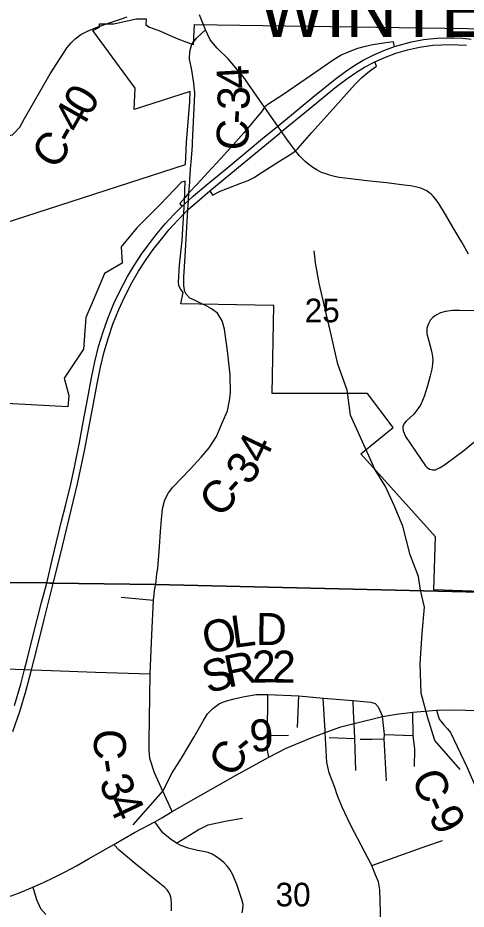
# Model space of a CAD drawing. Extents: x 0 to 34, y 0 to 22.
# Drawn here: x 5.55 to 6.345, y 15.187 to 16.768 of the extents above; entities that cross this region are included whole.
import ezdxf

# ---------------------------------------------------------------- set-up
doc = ezdxf.new("R2010")
doc.units = 0
for name, color, linetype in [('GM_X_City_Street', 7, 'Continuous'), ('GM_X_Corporation', 7, 'Continuous'), ('GM_X_Corporation_Text', 7, 'Continuous'), ('GM_X_County_Road', 7, 'Continuous'), ('GM_X_County_Road_Text', 7, 'Continuous'), ('GM_X_Interchange_Ramps', 7, 'Continuous'), ('GM_X_Minor_River', 7, 'Continuous'), ('GM_X_Section_Text', 7, 'Continuous'), ('GM_X_State_Route', 7, 'Continuous'), ('GM_X_Township_Road', 7, 'Continuous'), ('GM_X_US_Route', 7, 'Continuous')]:
    doc.layers.add(name, color=color, linetype=linetype)

msp = doc.modelspace()

# ---------------------------------------------------------------- linework, layer by layer
at = {"layer": 'GM_X_City_Street'}
msp.add_lwpolyline([(6.3629, 16.2484), (6.3334, 16.2491), (6.3214, 16.249), (6.3088, 16.2475), (6.2999, 16.2448), (6.2909, 16.2404), (6.2864, 16.2369), (6.2821, 16.2324), (6.2785, 16.2254), (6.2756, 16.2176), (6.2754, 16.2126), (6.2757, 16.2078), (6.2784, 16.1973), (6.2834, 16.1791), (6.2854, 16.1713), (6.2861, 16.1624), (6.2855, 16.1542), (6.2844, 16.145), (6.2815, 16.133), (6.2767, 16.1154), (6.271, 16.0965), (6.2648, 16.0826), (6.2595, 16.0746), (6.2524, 16.0653), (6.239, 16.053), (6.2353, 16.0485), (6.2332, 16.0434), (6.233, 16.0398), (6.2337, 16.0356), (6.2353, 16.0313), (6.2378, 16.0259), (6.2731, 15.9738), (6.2764, 15.9705), (6.2803, 15.9677), (6.2855, 15.9662), (6.2908, 15.9664), (6.2992, 15.9705), (6.3068, 15.9754), (6.3279, 15.9905), (6.3412, 16.0009), (6.359, 16.0156)], dxfattribs=at)
at = {"layer": 'GM_X_Corporation'}
for points in [[(5.5242, 16.4033), (5.8477, 16.5082), (5.849, 16.5474), (5.8549, 16.6198), (5.8559, 16.6377), (5.7562, 16.6054), (5.7582, 16.6432), (5.6829, 16.7458), (5.6949, 16.7513), (5.695, 16.7575), (5.7204, 16.7575), (5.7598, 16.7663), (5.7775, 16.7663), (5.7771, 16.7554), (5.7838, 16.7518), (5.8029, 16.7442), (5.8309, 16.7322), (5.8462, 16.7264), (5.8617, 16.7206), (5.8618, 16.7216), (5.8633, 16.7565), (6.5495, 16.7462)], [(6.4714, 15.7474), (6.2879, 15.7537), (6.2911, 15.8475), (6.1587, 15.995), (6.2161, 16.0418), (6.1705, 16.1017), (6.001, 16.1021), (6.004, 16.258), (5.839, 16.2611), (5.8435, 16.281), (5.8378, 16.288), (5.8356, 16.2934), (5.8349, 16.2995), (5.8367, 16.3298), (5.8414, 16.3732), (5.8426, 16.3937), (5.8456, 16.4419), (5.8468, 16.4782), (5.8405, 16.4764), (5.8026, 16.4372), (5.761, 16.3957), (5.7334, 16.3617), (5.7349, 16.3331), (5.7037, 16.3144), (5.6835, 16.2669), (5.6707, 16.2368), (5.6667, 16.1803), (5.6321, 16.129), (5.6403, 16.0983), (5.6386, 16.0784), (5.5079, 16.0853)], [(5.4664, 15.7674), (5.6014, 15.7658), (5.6068, 15.7657), (5.6123, 15.7657), (5.7944, 15.7634), (6.4702, 15.7474), (6.8105, 15.7443), (6.8653, 15.7428), (6.9267, 15.7411), (7.0294, 15.7382), (7.1916, 15.7337), (7.2174, 15.7331), (7.2238, 15.7321), (7.3532, 15.7283), (7.8346, 15.7173), (8.2379, 15.708), (8.2436, 15.7079), (8.2556, 15.7096), (8.4088, 15.7047), (8.4164, 15.7046), (8.9, 15.6953), (8.9, 16.3396)], [(4.5503, 14.1), (8.9, 14.1), (8.9, 15.6953), (8.4164, 15.7046), (8.4088, 15.7047), (8.2556, 15.7096), (8.2436, 15.7079), (8.2379, 15.708), (7.8346, 15.7173), (7.3532, 15.7283), (7.2238, 15.7321), (7.2174, 15.7331), (7.1916, 15.7337), (7.0294, 15.7382), (6.9267, 15.7411), (6.8653, 15.7428), (6.8105, 15.7443), (6.4702, 15.7474), (5.7944, 15.7634), (5.6123, 15.7657), (5.6068, 15.7657), (5.6014, 15.7658), (5.4664, 15.7674)]]:
    msp.add_lwpolyline(points, dxfattribs=at)
at = {"layer": 'GM_X_County_Road'}
for p, q in [((5.8684, 16.7333), (5.8827, 16.7466)), ((5.8575, 16.5117), (5.8596, 16.5418))]:
    msp.add_line(p, q, dxfattribs=at)
for points in [[(5.671, 16.7433), (5.6735, 16.7446), (5.6892, 16.7508), (5.7074, 16.7573)], [(5.7074, 16.7573), (5.732, 16.7659), (5.7439, 16.7699)], [(5.3928, 16.5372), (5.3985, 16.541), (5.4132, 16.5466), (5.4712, 16.5579), (5.4999, 16.5533), (5.5403, 16.5604), (5.5534, 16.5743), (5.562, 16.5897), (5.6072, 16.6686), (5.6376, 16.7153), (5.6445, 16.724), (5.6518, 16.7306), (5.662, 16.7387), (5.671, 16.7433)], [(5.8635, 16.6394), (5.8624, 16.6525), (5.8585, 16.6755), (5.8548, 16.6953), (5.855, 16.7085), (5.8587, 16.7212), (5.8617, 16.7251), (5.8622, 16.7258)], [(5.8622, 16.7258), (5.867, 16.732), (5.8677, 16.7327), (5.8684, 16.7333)], [(5.8596, 16.5418), (5.86, 16.5468), (5.864, 16.6334), (5.8638, 16.6364), (5.8635, 16.6394)], [(5.8554, 16.4825), (5.8571, 16.5067), (5.8575, 16.5117)], [(5.8467, 16.345), (5.8515, 16.4273), (5.8527, 16.4444), (5.8536, 16.4576), (5.855, 16.4767), (5.8554, 16.4825)], [(5.8445, 16.296), (5.8447, 16.3088), (5.8467, 16.345)], [(5.8649, 16.2667), (5.8552, 16.2712), (5.8487, 16.2779), (5.8458, 16.2841), (5.8455, 16.2861), (5.8445, 16.293), (5.8445, 16.296)], [(5.7944, 15.7619), (5.7946, 15.7629), (5.7968, 15.7819), (5.7983, 15.7921), (5.8013, 15.8302), (5.8028, 15.8573), (5.8046, 15.8784), (5.8069, 15.8976), (5.811, 15.9133), (5.8175, 15.9258), (5.825, 15.9359), (5.8558, 15.9674), (5.8754, 15.9889), (5.8894, 16.0057), (5.9024, 16.0255), (5.9131, 16.051), (5.9222, 16.0714), (5.9258, 16.0897), (5.9271, 16.1029), (5.9265, 16.1348), (5.9222, 16.1778), (5.9168, 16.2158), (5.9123, 16.2309), (5.9041, 16.2441), (5.8935, 16.2521), (5.8853, 16.2567), (5.8755, 16.2617), (5.8649, 16.2667)], [(5.8236, 15.3605), (5.8072, 15.3964), (5.7925, 15.4292), (5.7841, 15.4543), (5.7828, 15.4694), (5.7828, 15.485), (5.7848, 15.6046), (5.7878, 15.6738), (5.7908, 15.7354), (5.7923, 15.7513), (5.7939, 15.759), (5.7944, 15.7619)], [(5.7544, 15.3372), (5.8072, 15.3964), (5.8238, 15.4292), (5.8405, 15.455), (5.8628, 15.4927), (5.8796, 15.5218), (5.8866, 15.5335), (5.8958, 15.5435), (5.9075, 15.5519), (5.9201, 15.5567), (5.9339, 15.5606), (5.9492, 15.5638), (5.9729, 15.5678), (5.9935, 15.568), (6.0483, 15.5654), (6.0915, 15.5616), (6.1449, 15.5575), (6.1766, 15.5545), (6.184, 15.5519), (6.1893, 15.5463), (6.1972, 15.5291)], [(6.1972, 15.5291), (6.2221, 15.533), (6.2511, 15.5366), (6.2927, 15.5405)], [(6.2927, 15.5405), (6.3175, 15.541), (6.371, 15.5398), (6.4077, 15.5372), (6.4382, 15.5331), (6.4667, 15.529)], [(6.2927, 15.5405), (6.2978, 15.5242), (6.3003, 15.5205), (6.3061, 15.514), (6.3122, 15.5073), (6.3174, 15.5004), (6.3474, 15.4383), (6.3618, 15.4045), (6.3711, 15.3851), (6.3807, 15.3689), (6.3866, 15.3614), (6.3929, 15.3557), (6.4036, 15.3508), (6.4096, 15.3495), (6.4166, 15.3492), (6.4241, 15.35), (6.4307, 15.3528), (6.4469, 15.3618), (6.4675, 15.3746), (6.5022, 15.3966), (6.5132, 15.4033)], [(5.8236, 15.3605), (5.8745, 15.3895), (5.936, 15.4246), (5.9665, 15.4409), (5.9954, 15.4572), (6.0262, 15.4727), (6.0702, 15.4914), (6.0951, 15.5007), (6.123, 15.5106), (6.1467, 15.5165), (6.1972, 15.5291)], [(5.7933, 15.3424), (5.8053, 15.3493), (5.8236, 15.3605)], [(5.72, 15.3019), (5.757, 15.3234), (5.7933, 15.3424)], [(5.5765, 15.2264), (5.5955, 15.2347), (5.6141, 15.2433), (5.6339, 15.2535), (5.654, 15.2644), (5.6751, 15.2766), (5.72, 15.3019)], [(5.8227, 15.1841), (5.8226, 15.197), (5.8219, 15.2062), (5.8202, 15.2125), (5.8175, 15.2179), (5.8149, 15.2214), (5.811, 15.2256), (5.8021, 15.233), (5.7594, 15.2674), (5.73, 15.2917), (5.72, 15.3019)], [(5.4875, 15.1929), (5.5249, 15.2062), (5.5509, 15.2158), (5.5765, 15.2264)]]:
    msp.add_lwpolyline(points, dxfattribs=at)
at = {"layer": 'GM_X_Interchange_Ramps'}
for points in [[(6.2181, 16.7174), (6.2164, 16.7253), (6.1989, 16.723), (6.1798, 16.7202), (6.1663, 16.7175), (6.1525, 16.7137), (6.1388, 16.7086), (6.1239, 16.7017), (6.1097, 16.6931), (6.096, 16.6835), (6.0595, 16.6589), (6.0202, 16.6318), (5.9938, 16.6145), (5.9876, 16.6096)], [(6.0424, 16.5325), (6.047, 16.5366), (6.0717, 16.5647), (6.1036, 16.6001), (6.1484, 16.6505), (6.1605, 16.6624), (6.1709, 16.6713), (6.1802, 16.6781), (6.1866, 16.6824), (6.1832, 16.6901)], [(5.9876, 16.6096), (5.9832, 16.6034), (5.9724, 16.5897), (5.9508, 16.5643), (5.9319, 16.5427), (5.9102, 16.5189), (5.8871, 16.4938), (5.868, 16.473), (5.8536, 16.4576), (5.8461, 16.4491)], [(5.8907, 16.4614), (5.8953, 16.4538), (5.9091, 16.4605), (5.9214, 16.4655), (5.9456, 16.4748), (5.9584, 16.4799), (5.9691, 16.4851), (5.9772, 16.49), (6.0095, 16.5108), (6.0363, 16.5274), (6.0424, 16.5325)], [(5.8461, 16.4491), (5.8372, 16.4389), (5.8409, 16.4335)]]:
    msp.add_lwpolyline(points, dxfattribs=at)
at = {"layer": 'GM_X_Minor_River'}
msp.add_lwpolyline([(6.3347, 15.4348), (6.2896, 15.4862), (6.2767, 15.5282), (6.2658, 15.5702), (6.2641, 15.6226), (6.2673, 15.6766), (6.2713, 15.7231), (6.2644, 15.753), (6.2609, 15.7772), (6.2463, 15.8157), (6.2332, 15.8668), (6.2175, 15.9034), (6.2021, 15.937), (6.1842, 15.9663), (6.1641, 16.0109), (6.1401, 16.0637), (6.1344, 16.108), (6.1177, 16.1537), (6.1063, 16.2037), (6.0952, 16.2514), (6.0849, 16.2976), (6.0779, 16.3336), (6.0769, 16.3446), (6.0756, 16.3548)], dxfattribs=at)
at = {"layer": 'GM_X_State_Route'}
for points in [[(5.9876, 16.6096), (5.9495, 16.6643), (5.9232, 16.6955), (5.9035, 16.7144), (5.8915, 16.7293), (5.8827, 16.7466), (5.8722, 16.7737)], [(6.0257, 16.5555), (6.0179, 16.5663), (6.0111, 16.5759), (5.9876, 16.6096)], [(6.0796, 16.499), (6.0736, 16.5026), (6.0662, 16.5081), (6.0598, 16.5133), (6.0496, 16.5231), (6.0424, 16.5325), (6.0257, 16.5555)], [(6.3496, 16.3492), (6.3375, 16.3704), (6.3219, 16.397), (6.3088, 16.4194), (6.2972, 16.4386), (6.2924, 16.4454), (6.2868, 16.4521), (6.2834, 16.4554), (6.2793, 16.4586), (6.2757, 16.4612), (6.2717, 16.4633), (6.2651, 16.466), (6.2582, 16.468), (6.2467, 16.4701), (6.2353, 16.4716), (6.2042, 16.4753), (6.1746, 16.4785), (6.14, 16.4824), (6.1199, 16.4851), (6.1117, 16.4867), (6.1038, 16.4888), (6.0963, 16.4912), (6.0886, 16.4941), (6.0813, 16.498), (6.0796, 16.499)]]:
    msp.add_lwpolyline(points, dxfattribs=at)
at = {"layer": 'GM_X_Township_Road'}
for p, q in [((5.7331, 15.7404), (5.7908, 15.7354)), ((6.0461, 15.5095), (6.0483, 15.5654)), ((6.095, 15.5036), (6.0915, 15.5616)), ((5.9931, 15.4954), (6.0301, 15.4958)), ((6.1024, 15.4916), (6.1479, 15.4898)), ((6.2007, 15.4971), (6.2517, 15.4955)), ((6.1572, 15.4886), (6.1786, 15.4889)), ((6.1786, 15.4889), (6.2, 15.4892))]:
    msp.add_line(p, q, dxfattribs=at)
for points in [[(5.4535, 15.6162), (5.4622, 15.6159), (5.5619, 15.6123), (5.5742, 15.6117), (5.6094, 15.6105)], [(5.6094, 15.6105), (5.6875, 15.6078), (5.7848, 15.6046)], [(5.9954, 15.4572), (5.993, 15.4686), (5.9931, 15.4954), (5.9935, 15.568)], [(6.1494, 15.4333), (6.1479, 15.4898), (6.1467, 15.5165), (6.1453, 15.5374), (6.1449, 15.5575)], [(6.2043, 15.4148), (6.2, 15.4892), (6.2007, 15.4971), (6.1972, 15.5291)], [(6.2538, 15.4404), (6.2542, 15.4713), (6.2517, 15.4955), (6.2511, 15.5366)], [(6.1941, 15.1621), (6.1925, 15.2217), (6.1902, 15.2356), (6.1848, 15.2484), (6.1778, 15.2645), (6.1404, 15.3372), (6.1254, 15.3685), (6.1168, 15.3902), (6.1124, 15.4031), (6.1025, 15.4291), (6.0982, 15.4475), (6.0951, 15.5007), (6.095, 15.5036)], [(5.9478, 15.1806), (5.9492, 15.1875), (5.9496, 15.1955), (5.9476, 15.2045), (5.9441, 15.2152), (5.9387, 15.2313), (5.931, 15.2497), (5.9261, 15.2579), (5.9222, 15.2629), (5.9161, 15.2698), (5.9089, 15.2755), (5.9022, 15.28), (5.8946, 15.285), (5.8875, 15.2876), (5.8664, 15.2922), (5.8523, 15.2955), (5.8379, 15.3011), (5.8314, 15.3044), (5.82, 15.3119), (5.8075, 15.3228), (5.7933, 15.3424)], [(5.8314, 15.3044), (5.87, 15.3281), (5.8876, 15.337), (5.9207, 15.3441), (5.9485, 15.349)], [(6.1778, 15.2645), (6.2756, 15.2997), (6.3032, 15.3092)], [(5.5765, 15.2264), (5.583, 15.2043), (5.5903, 15.1885), (5.5997, 15.1779)]]:
    msp.add_lwpolyline(points, dxfattribs=at)
at = {"layer": 'GM_X_US_Route'}
for points in [[(6.2181, 16.7174), (6.2484, 16.7256), (6.2696, 16.7294), (6.2817, 16.731), (6.2941, 16.7321), (6.3104, 16.7327), (6.3242, 16.7328), (6.3395, 16.732), (6.3544, 16.7305)], [(5.8409, 16.4335), (5.8527, 16.4444), (5.8609, 16.452), (5.8839, 16.4711), (5.9197, 16.5006), (5.955, 16.5296), (5.9843, 16.5539), (6.0111, 16.5759), (6.0494, 16.6074), (6.0734, 16.6273), (6.1128, 16.6592), (6.1312, 16.6731), (6.1481, 16.6844), (6.1627, 16.6929), (6.1804, 16.7021), (6.1996, 16.7104), (6.2181, 16.7174)], [(6.0148, 16.5637), (6.0179, 16.5663), (6.0623, 16.6026), (6.1155, 16.6462), (6.1339, 16.6602), (6.1509, 16.6719), (6.1652, 16.6805), (6.1832, 16.6901), (6.2021, 16.6986), (6.2206, 16.7056), (6.2411, 16.7115), (6.2629, 16.7162), (6.2742, 16.7181), (6.2864, 16.7194), (6.3024, 16.7205), (6.316, 16.7208), (6.3313, 16.7205), (6.3459, 16.7194)], [(5.853, 16.4286), (5.8683, 16.442), (5.8907, 16.4614), (5.9616, 16.5196), (6.0148, 16.5637)], [(5.541, 15.5026), (5.5533, 15.5378), (5.5648, 15.5755), (5.5742, 15.6117), (5.5835, 15.6487), (5.5967, 15.7011), (5.6125, 15.7651), (5.6249, 15.8141), (5.6413, 15.8803), (5.656, 15.9416), (5.6685, 16.0004), (5.6802, 16.0621), (5.6916, 16.1219), (5.6966, 16.1488), (5.703, 16.1755), (5.7106, 16.2014), (5.7187, 16.2251), (5.7289, 16.2509), (5.739, 16.2725), (5.7526, 16.2991), (5.7642, 16.3188), (5.7777, 16.3395), (5.7901, 16.3573), (5.8046, 16.3757), (5.8187, 16.3929), (5.834, 16.4094), (5.8476, 16.4234), (5.8515, 16.4273), (5.853, 16.4286)], [(5.544, 15.5488), (5.5553, 15.5862), (5.5619, 15.6123), (5.5666, 15.6303), (5.5738, 15.659), (5.5843, 15.7013), (5.5918, 15.7312), (5.6016, 15.7653), (5.6112, 15.8091), (5.6187, 15.8386), (5.6277, 15.8755), (5.6351, 15.9048), (5.6437, 15.9413), (5.6503, 15.9711), (5.6593, 16.0151), (5.6665, 16.054), (5.6733, 16.091), (5.6805, 16.1294), (5.6865, 16.1583), (5.6932, 16.1853), (5.7012, 16.2115), (5.7096, 16.2351), (5.7204, 16.2612), (5.7303, 16.2823), (5.7446, 16.3092), (5.7565, 16.3291), (5.7693, 16.3488), (5.7828, 16.3674), (5.7964, 16.385), (5.8115, 16.4027), (5.827, 16.4194), (5.8409, 16.4335)]]:
    msp.add_lwpolyline(points, dxfattribs=at)

# ---------------------------------------------------------------- texts
at = {"layer": 'GM_X_Corporation_Text'}
msp.add_text('WINTERSVILLE', height=0.094697, rotation=0, dxfattribs=at).set_placement((5.9768, 16.7339))
at = {"layer": 'GM_X_County_Road_Text'}
for s, rotation, p in [('4', 93.1496, (5.9611, 16.6432)), ('0', 59.6877, (5.6764, 16.5909)), ('3', 89.8258, (5.9611, 16.6046)), ('4', 60.2635, (5.6591, 16.5606)), ('-', 88.1821, (5.9603, 16.5795)), ('C', 87.5989, (5.9584, 16.5322)), ('-', 60.6035, (5.6477, 16.5404)), ('C', 53.4369, (5.6156, 16.4964)), ('4', 64.4482, (5.9864, 15.9746)), ('3', 54.431, (5.9605, 15.9368)), ('C', 46.8659, (5.9078, 15.8791)), ('-', 47.8984, (5.9404, 15.914)), ('O', 14.7404, (5.8857, 15.638)), ('L', 7.7725, (5.9323, 15.6504)), ('D', 359.4427, (5.9722, 15.656)), ('S', 17.6086, (5.8879, 15.5688)), ('R', 11.4768, (5.9229, 15.58)), ('2', 0.8327, (5.9658, 15.589)), ('2', 358.8655, (6.0003, 15.5895)), ('9', 4.6145, (5.9636, 15.4657)), ('C', 269.356, (5.6853, 15.5071)), ('C', 60.0116, (5.9343, 15.4184)), ('-', 39.0375, (5.9539, 15.4544)), ('-', 278.9503, (5.6855, 15.45)), ('C', 293.1402, (6.2472, 15.4212)), ('3', 292.3293, (5.693, 15.4131)), ('4', 295.143, (5.7075, 15.3779)), ('-', 294.5129, (6.2661, 15.3769)), ('9', 297.9513, (6.2775, 15.3523))]:
    msp.add_text(s, height=0.0568, rotation=rotation, dxfattribs=at).set_placement(p)
at = {"layer": 'GM_X_Section_Text'}
for s, p in [('25', (6.0589, 16.2282)), ('30', (6.0072, 15.1923))]:
    msp.add_text(s, height=0.04186, rotation=0, dxfattribs=at).set_placement(p)

doc.saveas('drawing.dxf')
